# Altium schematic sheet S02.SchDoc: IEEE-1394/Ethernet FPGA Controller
size 381 x 254 mm; Revision: 3.2; SheetNumber: 2; SheetTotal: 10
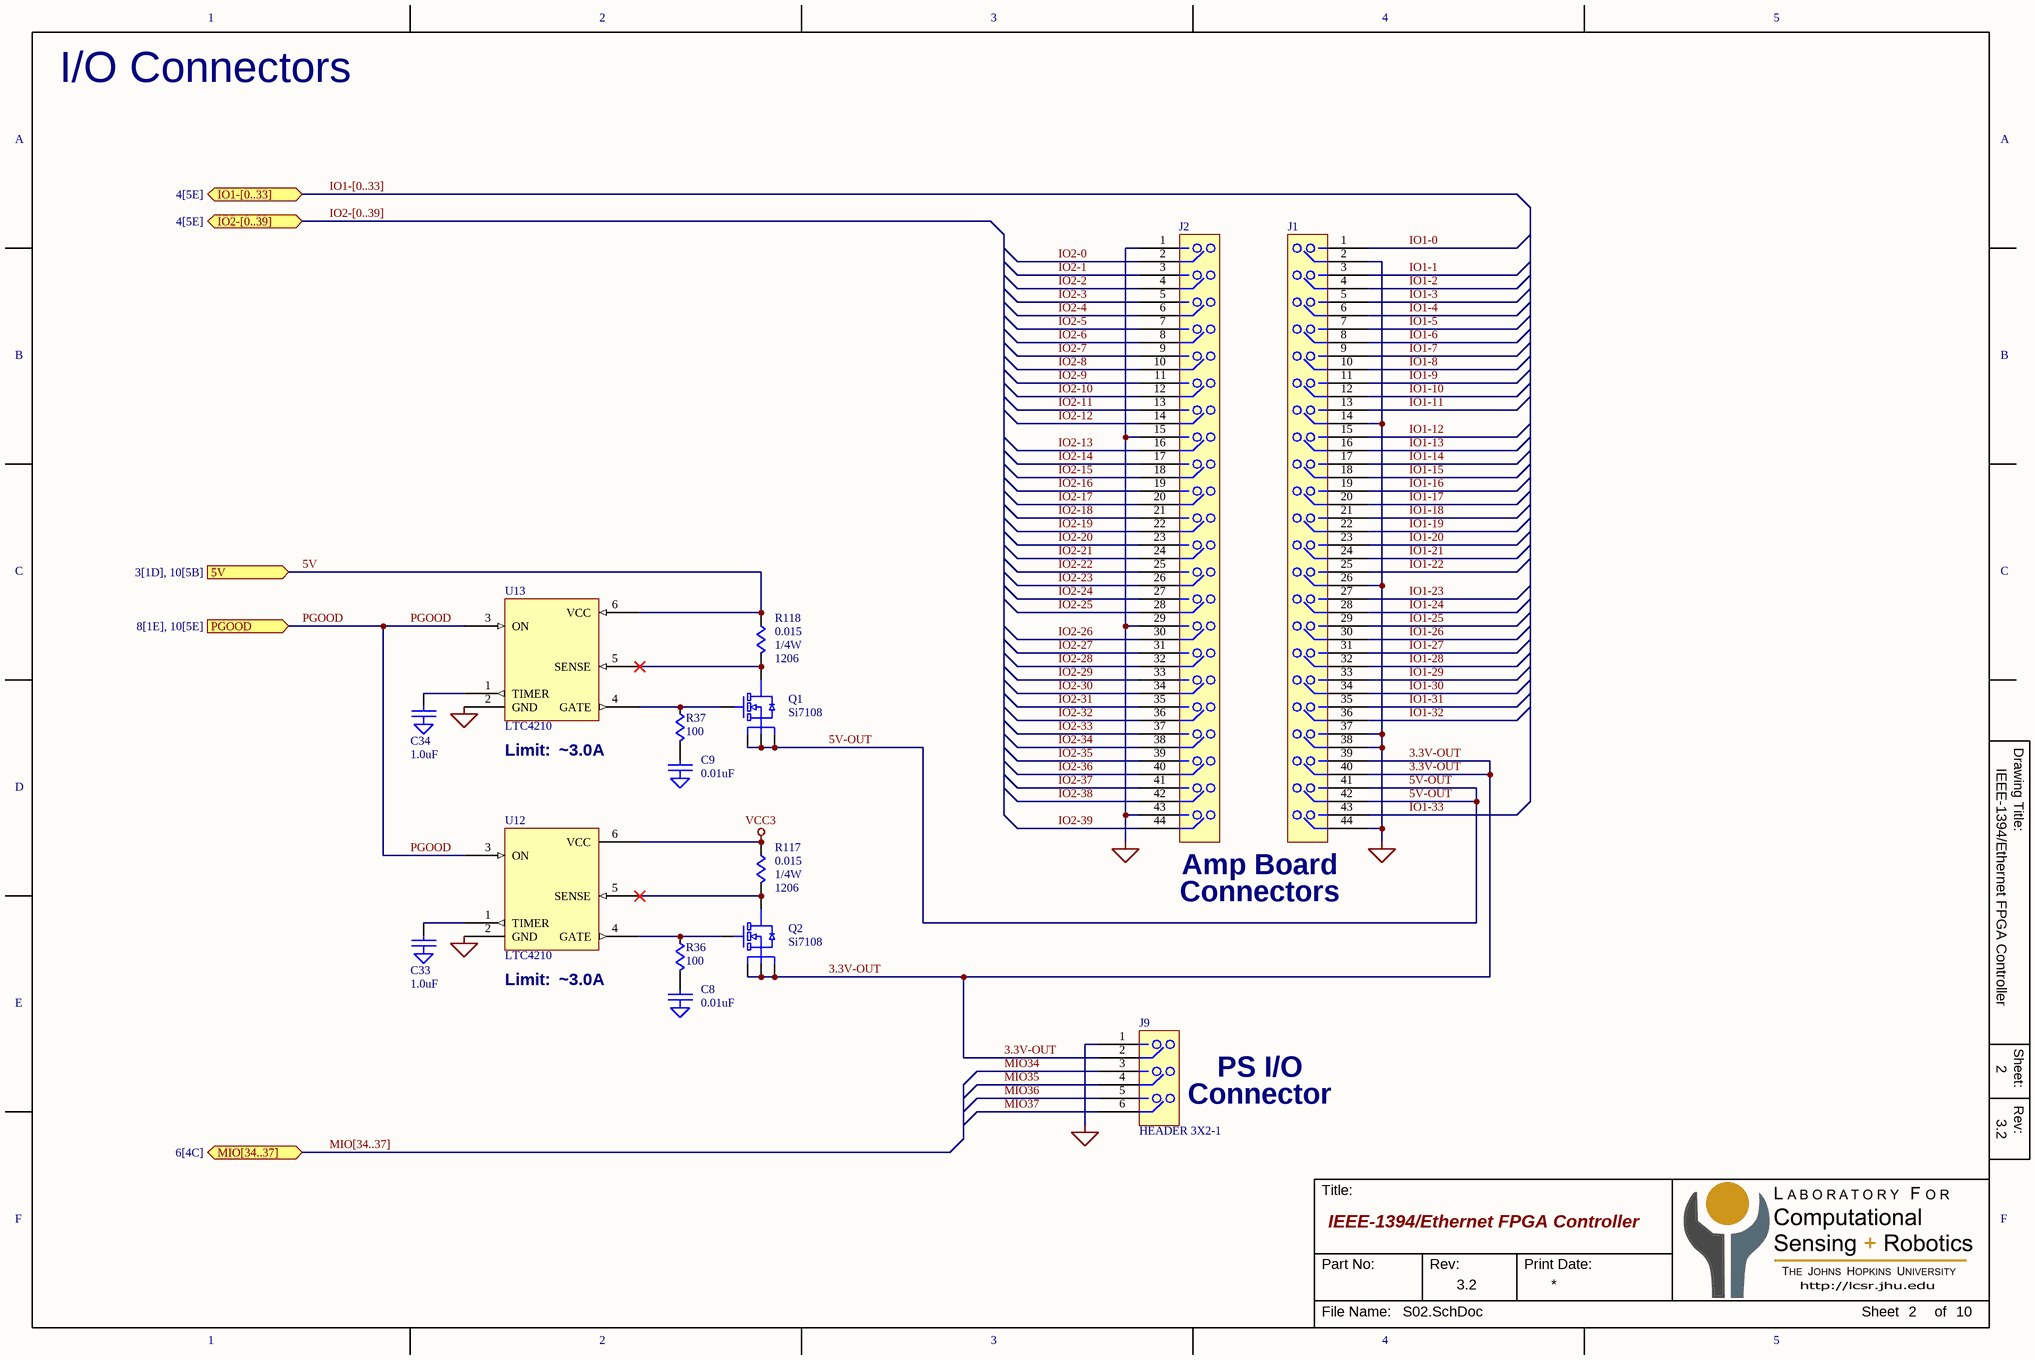
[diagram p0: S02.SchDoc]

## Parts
C8  0.01uF  [C0402]
C9  0.01uF  [C0402]
C33  1.0uF  [C0402]
C34  1.0uF  [C0402]
J1  HEADER 22x2-1  [HDR-22x2-2MM]  (value not drawn)
J2  HEADER 22x2-1  [HDR-22x2-2MM]  (value not drawn)
J9  HEADER 3X2-1  [HDR-3x2-2MM]
Q1  Si7108  [PowerPak-1212]
Q2  Si7108  [PowerPak-1212]
R36  100  [R0402]
R37  100  [R0402]
R117  0.015  Power: 1/4W  Type: 1206  [R1206]
R118  0.015  Power: 1/4W  Package: 1206  [R1206]
U12  LTC4210  [SOT-23-6]
U13  LTC4210  [SOT-23-6]

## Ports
5V (in, see 3[1D], 10[5B]), IO1-[0..33] (bidir, see 4[5E]), IO2-[0..39] (bidir, see 4[5E]), MIO[34..37] (bidir, see 6[4C]), PGOOD (in, see 8[1E], 10[5E])

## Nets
GND: C8.2(GND) C9.2(GND) C33.2(GND) C34.2(GND) J1.2 J1.14 J1.26 J1.37 J1.38 J1.44 J2.1 J2.15 J2.29 J2.43 J9.1 U12.2(GND) U13.2(GND)
VCC3: R117.1 U12.6(VCC)
3.3V-OUT: J1.39 J1.40 J9.2 Q2.1(S) Q2.2(S) Q2.3(S)
5V: R118.1 U13.6(VCC) ; port 5V
5V-OUT: J1.41 J1.42 Q1.1(S) Q1.2(S) Q1.3(S)
IO1-0: J1.1
IO1-1: J1.3
IO1-2: J1.4
IO1-3: J1.5
IO1-4: J1.6
IO1-5: J1.7
IO1-6: J1.8
IO1-7: J1.9
IO1-8: J1.10
IO1-9: J1.11
IO1-10: J1.12
IO1-11: J1.13
IO1-12: J1.15
IO1-13: J1.16
IO1-14: J1.17
IO1-15: J1.18
IO1-16: J1.19
IO1-17: J1.20
IO1-18: J1.21
IO1-19: J1.22
IO1-20: J1.23
IO1-21: J1.24
IO1-22: J1.25
IO1-23: J1.27
IO1-24: J1.28
IO1-25: J1.29
IO1-26: J1.30
IO1-27: J1.31
IO1-28: J1.32
IO1-29: J1.33
IO1-30: J1.34
IO1-31: J1.35
IO1-32: J1.36
IO1-33: J1.43
IO2-0: J2.2
IO2-1: J2.3
IO2-2: J2.4
IO2-3: J2.5
IO2-4: J2.6
IO2-5: J2.7
IO2-6: J2.8
IO2-7: J2.9
IO2-8: J2.10
IO2-9: J2.11
IO2-10: J2.12
IO2-11: J2.13
IO2-12: J2.14
IO2-13: J2.16
IO2-14: J2.17
IO2-15: J2.18
IO2-16: J2.19
IO2-17: J2.20
IO2-18: J2.21
IO2-19: J2.22
IO2-20: J2.23
IO2-21: J2.24
IO2-22: J2.25
IO2-23: J2.26
IO2-24: J2.27
IO2-25: J2.28
IO2-26: J2.30
IO2-27: J2.31
IO2-28: J2.32
IO2-29: J2.33
IO2-30: J2.34
IO2-31: J2.35
IO2-32: J2.36
IO2-33: J2.37
IO2-34: J2.38
IO2-35: J2.39
IO2-36: J2.40
IO2-37: J2.41
IO2-38: J2.42
IO2-39: J2.44
MIO34: J9.3
MIO35: J9.4
MIO36: J9.5
MIO37: J9.6
PGOOD: U12.3(ON) U13.3(ON) ; port PGOOD
NetC8_1: C8.1 R36.2
NetC9_1: C9.1 R37.2
NetC33_1: C33.1 U12.1(TIMER)
NetC34_1: C34.1 U13.1(TIMER)
NetQ1_4: Q1.4(G) R37.1 U13.4(GATE)
NetQ1_5: Q1.5(D) R118.2 U13.5(SENSE)
NetQ2_4: Q2.4(G) R36.1 U12.4(GATE)
NetQ2_5: Q2.5(D) R117.2 U12.5(SENSE)

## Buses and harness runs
bus IO1-[0..33] = port IO1-[0..33]
bus IO2-[0..39] = port IO2-[0..39]
bus MIO[34..37] = port MIO[34..37]

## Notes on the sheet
- I/O Connectors
- (near U13) Limit:
- (near U13) ~3.0A
- Amp Board
- Connectors
- (near U12) Limit:
- (near U12) ~3.0A
- PS I/O
- Connector

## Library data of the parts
C8 C9 C33 C34 = CAP-GND
Q1 Q2 = MOSFET-N-PPACK
R36 R37 = R-MINI
R117 R118 = R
